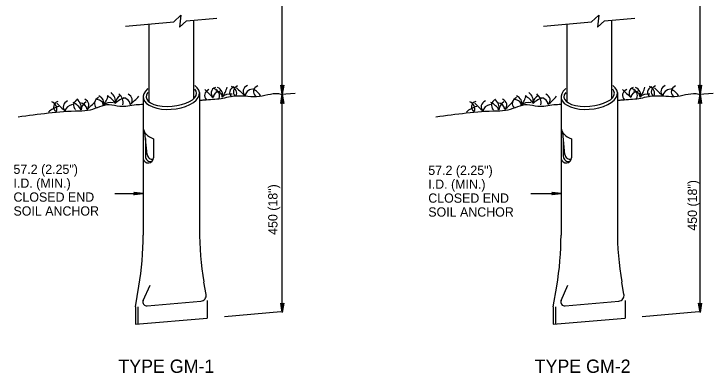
# Model space of a CAD drawing. Extents: x 640253 to 641999, y 298458 to 299646.
# Drawn here: x 640664.1 to 640890, y 299353.4 to 299469.6 of the extents above; entities that cross this region are included whole.
import ezdxf

# ---------------------------------------------------------------- set-up
doc = ezdxf.new("R2010")
doc.units = 0
doc.layers.add('2', color=7, linetype='Continuous')

msp = doc.modelspace()

# ---------------------------------------------------------------- linework, layer by layer
at = {"layer": '2'}
for p, q in [((640750.8, 299443.58), (640750.8, 299512.4)), ((640885.87, 299443.58), (640885.87, 299512.4)), ((640715.71, 299466.98), (640718.01, 299469.2)), ((640718.01, 299469.2), (640717.61, 299465.31)), ((640719.88, 299467.35), (640729.7, 299468.21)), ((640850.79, 299466.98), (640853.09, 299469.2)), ((640853.09, 299469.2), (640852.69, 299465.31)), ((640854.96, 299467.35), (640864.78, 299468.21)), ((640700.17, 299465.61), (640715.71, 299466.98)), ((640707.71, 299466.28), (640707.71, 299441.18)), ((640717.61, 299465.31), (640719.88, 299467.35)), ((640722.17, 299467.55), (640722.17, 299442.19)), ((640835.25, 299465.61), (640850.79, 299466.98)), ((640842.79, 299466.28), (640842.79, 299441.18)), ((640852.69, 299465.31), (640854.96, 299467.35)), ((640857.25, 299467.55), (640857.25, 299442.19)), ((640724.04, 299444.16), (640724.04, 299399.89)), ((640750.5, 299443.61), (640754.97, 299444)), ((640750.8, 299373), (640750.8, 299443.58)), ((640859.12, 299444.16), (640859.12, 299399.89)), ((640885.57, 299443.61), (640890.05, 299444)), ((640885.87, 299373), (640885.87, 299443.58)), ((640705.85, 299442.57), (640705.85, 299398.05)), ((640840.92, 299442.57), (640840.92, 299398.05)), ((640707.11, 299424.14), (640706.38, 299431.28)), ((640706.58, 299429.29), (640706.58, 299423.53)), ((640842.19, 299424.14), (640841.45, 299431.28)), ((640841.66, 299429.29), (640841.66, 299423.53)), ((640709.23, 299429.14), (640709.23, 299423.08)), ((640844.31, 299429.14), (640844.31, 299423.08)), ((640696.66, 299411.48), (640705.85, 299411.48)), ((640831.11, 299411.48), (640840.92, 299411.48)), ((640705.88, 299376.89), (640708.08, 299381.83)), ((640726.2, 299378.84), (640725.5, 299382.86)), ((640840.96, 299376.89), (640843.16, 299381.83)), ((640861.27, 299378.84), (640860.58, 299382.86)), ((640703.35, 299374.8), (640704.47, 299381.53)), ((640838.42, 299374.8), (640839.55, 299381.53)), ((640707.13, 299375.13), (640724.51, 299376.66)), ((640726.54, 299376.84), (640726.54, 299371.21)), ((640842.21, 299375.13), (640859.59, 299376.66)), ((640861.62, 299376.84), (640861.62, 299371.21)), ((640703.35, 299374.8), (640703.35, 299369.18)), ((640704.1, 299374.8), (640704.1, 299369.18)), ((640732.12, 299371.7), (640750.34, 299373.3)), ((640838.42, 299374.8), (640838.42, 299369.18)), ((640839.17, 299374.8), (640839.17, 299369.18)), ((640867.2, 299371.7), (640885.42, 299373.3)), ((640703.35, 299369.18), (640726.54, 299371.21)), ((640838.42, 299369.18), (640861.62, 299371.21))]:
    msp.add_line(p, q, dxfattribs=at)
for points in [[(640751.15, 299446.43), (640750.95, 299446.33), (640750.8, 299443.58), (640751.15, 299446.43), (640751.28, 299446.58), (640750.8, 299443.58), (640750.66, 299446.33), (640750.46, 299446.43), (640750.8, 299443.58), (640750.32, 299446.58), (640750.46, 299446.43)], [(640886.23, 299446.43), (640886.03, 299446.33), (640885.87, 299443.58), (640886.23, 299446.43), (640886.36, 299446.58), (640885.87, 299443.58), (640885.74, 299446.33), (640885.54, 299446.43), (640885.87, 299443.58), (640885.4, 299446.58), (640885.54, 299446.43)], [(640750.44, 299440.73), (640750.64, 299440.83), (640750.8, 299443.58), (640750.44, 299440.73), (640750.31, 299440.58), (640750.8, 299443.58), (640750.93, 299440.83), (640751.14, 299440.73), (640750.8, 299443.58), (640751.27, 299440.58), (640751.14, 299440.73)], [(640885.52, 299440.73), (640885.72, 299440.83), (640885.87, 299443.58), (640885.52, 299440.73), (640885.39, 299440.58), (640885.87, 299443.58), (640886.01, 299440.83), (640886.21, 299440.73), (640885.87, 299443.58), (640886.35, 299440.58), (640886.21, 299440.73)], [(640702.99, 299411.84), (640703.1, 299411.63), (640705.85, 299411.48), (640702.99, 299411.84), (640702.85, 299411.97), (640705.85, 299411.48), (640703.1, 299411.35), (640703, 299411.14), (640705.85, 299411.48), (640702.85, 299411.01), (640703, 299411.14)], [(640838.07, 299411.84), (640838.18, 299411.63), (640840.92, 299411.48), (640838.07, 299411.84), (640837.92, 299411.97), (640840.92, 299411.48), (640838.18, 299411.35), (640838.08, 299411.14), (640840.92, 299411.48), (640837.92, 299411.01), (640838.08, 299411.14)], [(640751.15, 299375.85), (640750.95, 299375.75), (640750.8, 299373), (640751.15, 299375.85), (640751.28, 299376), (640750.8, 299373), (640750.66, 299375.75), (640750.46, 299375.85), (640750.8, 299373), (640750.32, 299376), (640750.46, 299375.85)], [(640886.23, 299375.85), (640886.03, 299375.75), (640885.87, 299373), (640886.23, 299375.85), (640886.36, 299376), (640885.87, 299373), (640885.74, 299375.75), (640885.54, 299375.85), (640885.87, 299373), (640885.4, 299376), (640885.54, 299375.85)]]:
    msp.add_lwpolyline(points, dxfattribs=at)
for centre, radius, start, end in [((640707.52, 299423.08), 1.71, 192.66, 0.0738), ((640708.29, 299423.53), 1.71, 179.9932, 284.9823), ((640708.82, 299424.32), 1.71, 185.8874, 282.1164), ((640842.6, 299423.08), 1.71, 192.66, 0.0738), ((640843.37, 299423.53), 1.71, 179.9932, 284.9823), ((640843.89, 299424.32), 1.71, 185.8874, 282.1164), ((640824.04, 299399.89), 100, 180, 189.8017), ((640959.12, 299399.89), 100, 180, 189.8017), ((640605.85, 299398.04), 100, 350.4939, 0), ((640740.92, 299398.04), 100, 350.4939, 0), ((640724.35, 299378.52), 1.88, 275.0167, 9.777), ((640859.43, 299378.52), 1.88, 275.0167, 9.777), ((640707.02, 299376.38), 1.25, 156.0017, 275.0122), ((640842.1, 299376.38), 1.25, 156.0017, 275.0122)]:
    msp.add_arc(centre, radius, start, end, dxfattribs=at)
for centre, major_axis, ratio, start_param, end_param in [((640714.94, 299443.36), (9.1, 0.8), 0.505377, 2.51251, 6.824211), ((640714.94, 299443.36), (8.14, 0.71), 0.446872, 5.874248, 6.61394), ((640728.37, 299443.25), (-2.67, 0), 0.81, 5.220291, 6.986898), ((640758.27, 299465.19), (-40.88, 0), 0.81, 0.65051, 0.753153), ((640730.48, 299443.94), (-2.67, 0), 0.81, 5.220291, 6.986898), ((640727.37, 299443.11), (3.17, 0), 0.81, 5.950888, 7.353079), ((640728.37, 299443.53), (3.17, 0), 0.81, 5.950888, 7.353079), ((640721.23, 299447.88), (12, 0), 0.81, 5.719284, 6.075734), ((640736.45, 299444.15), (-2.67, 0), 0.81, 5.220291, 6.986898), ((640732.91, 299443.89), (3.17, 0), 0.81, 5.950888, 7.353079), ((640737.67, 299444.4), (-2.67, 0), 0.81, 5.220291, 6.986898), ((640768.6, 299465.78), (-40.88, 0), 0.81, 0.65051, 0.753153), ((640740.82, 299444.53), (-2.67, 0), 0.81, 5.220291, 6.986898), ((640741.53, 299443.02), (-2.76, 0), 0.81, 4.863472, 6.233126), ((640737.48, 299440.47), (7.12, 0), 0.81, 0.438834, 0.99788), ((640744.16, 299444.4), (-2.67, 0), 0.81, 5.220291, 6.986898), ((640850.02, 299443.36), (9.1, 0.8), 0.505377, 2.51251, 6.824211), ((640850.02, 299443.36), (8.14, 0.71), 0.446872, 5.874248, 6.61394), ((640863.44, 299443.25), (-2.67, 0), 0.81, 5.220291, 6.986898), ((640893.35, 299465.19), (-40.88, 0), 0.81, 0.65051, 0.753153), ((640865.56, 299443.94), (-2.67, 0), 0.81, 5.220291, 6.986898), ((640862.45, 299443.11), (3.17, 0), 0.81, 5.950888, 7.353079), ((640863.45, 299443.53), (3.17, 0), 0.81, 5.950888, 7.353079), ((640856.31, 299447.88), (12, 0), 0.81, 5.719284, 6.075734), ((640871.52, 299444.15), (-2.67, 0), 0.81, 5.220291, 6.986898), ((640867.99, 299443.89), (3.17, 0), 0.81, 5.950888, 7.353079), ((640872.75, 299444.4), (-2.67, 0), 0.81, 5.220291, 6.986898), ((640903.68, 299465.78), (-40.88, 0), 0.81, 0.65051, 0.753153), ((640875.9, 299444.53), (-2.67, 0), 0.81, 5.220291, 6.986898), ((640876.61, 299443.02), (-2.76, 0), 0.81, 4.863472, 6.233126), ((640872.56, 299440.47), (7.12, 0), 0.81, 0.438834, 0.99788), ((640879.23, 299444.4), (-2.67, 0), 0.81, 5.220291, 6.986898), ((640689.95, 299440.82), (3.17, 0), 0.81, 5.950888, 7.353079), ((640682.81, 299445.17), (12, 0), 0.81, 5.719284, 6.075734), ((640690.38, 299438.2), (7.12, 0), 0.81, 0.438834, 0.99788), ((640691.96, 299441.33), (4.93, 0), 0.81, 6.111626, 7.062961), ((640701.43, 299440.4), (-4.62, 0), 0.81, 5.422128, 6.217327), ((640694.47, 299440.9), (4.93, 0), 0.81, 6.111626, 7.062961), ((640699.66, 299441.74), (2.67, 0), 0.81, 5.579472, 7.346079), ((640671.87, 299462.99), (40.88, 0), 0.81, 5.530032, 5.632675), ((640714.94, 299443.36), (8.14, 0.71), 0.446872, 2.733251, 5.87413), ((640731.2, 299442.43), (-2.76, 0), 0.81, 4.863472, 6.233126), ((640729.17, 299442.8), (2.21, 0), 0.81, 6.222188, 7.802691), ((640733.75, 299441.32), (-2.92, 0), 0.81, 4.426104, 5.665423), ((640825.03, 299440.82), (3.17, 0), 0.81, 5.950888, 7.353079), ((640817.89, 299445.17), (12, 0), 0.81, 5.719284, 6.075734), ((640825.45, 299438.2), (7.12, 0), 0.81, 0.438834, 0.99788), ((640827.04, 299441.33), (4.93, 0), 0.81, 6.111626, 7.062961), ((640836.51, 299440.4), (-4.62, 0), 0.81, 5.422128, 6.217327), ((640829.55, 299440.9), (4.93, 0), 0.81, 6.111626, 7.062961), ((640834.74, 299441.74), (2.67, 0), 0.81, 5.579472, 7.346079), ((640806.95, 299462.99), (40.88, 0), 0.81, 5.530032, 5.632675), ((640850.02, 299443.36), (8.14, 0.71), 0.446872, 2.733251, 5.87413), ((640866.28, 299442.43), (-2.76, 0), 0.81, 4.863472, 6.233126), ((640864.25, 299442.8), (2.21, 0), 0.81, 6.222188, 7.802691), ((640868.83, 299441.32), (-2.92, 0), 0.81, 4.426104, 5.665423), ((640674.79, 299438.91), (3.17, 0), 0.81, 5.950888, 7.353079), ((640679.55, 299439.42), (-2.67, 0), 0.81, 5.220291, 6.986898), ((640710.48, 299460.8), (-40.88, 0), 0.81, 0.65051, 0.753153), ((640682.7, 299439.55), (-2.67, 0), 0.81, 5.220291, 6.986898), ((640679.33, 299436.11), (7.12, 0), 0.81, 0.438834, 0.99788), ((640686, 299440.04), (-2.67, 0), 0.81, 5.220291, 6.986898), ((640680.91, 299439.24), (4.93, 0), 0.81, 6.111626, 7.062961), ((640684.94, 299438.61), (2.76, 0), 0.81, 0.050059, 1.419713), ((640690.38, 299438.31), (-4.62, 0), 0.81, 5.422128, 6.217327), ((640685.65, 299440.12), (2.67, 0), 0.81, 5.579472, 7.346079), ((640657.87, 299461.37), (40.88, 0), 0.81, 5.530032, 5.632675), ((640692.75, 299440.62), (-2.67, 0), 0.81, 5.220291, 6.986898), ((640690.75, 299440.09), (2.21, 0), 0.81, 6.222188, 7.802691), ((640695.33, 299438.61), (-2.92, 0), 0.81, 4.426104, 5.665423), ((640702.01, 299437.27), (-6.66, 0), 0.81, 4.996122, 5.605504), ((640698.94, 299440.23), (2.76, 0), 0.81, 0.050059, 1.419713), ((640809.87, 299438.91), (3.17, 0), 0.81, 5.950888, 7.353079), ((640814.63, 299439.42), (-2.67, 0), 0.81, 5.220291, 6.986898), ((640845.56, 299460.8), (-40.88, 0), 0.81, 0.65051, 0.753153), ((640817.77, 299439.55), (-2.67, 0), 0.81, 5.220291, 6.986898), ((640814.41, 299436.11), (7.12, 0), 0.81, 0.438834, 0.99788), ((640821.08, 299440.04), (-2.67, 0), 0.81, 5.220291, 6.986898), ((640815.99, 299439.24), (4.93, 0), 0.81, 6.111626, 7.062961), ((640820.02, 299438.61), (2.76, 0), 0.81, 0.050059, 1.419713), ((640825.46, 299438.31), (-4.62, 0), 0.81, 5.422128, 6.217327), ((640820.73, 299440.12), (2.67, 0), 0.81, 5.579472, 7.346079), ((640792.95, 299461.37), (40.88, 0), 0.81, 5.530032, 5.632675), ((640827.83, 299440.62), (-2.67, 0), 0.81, 5.220291, 6.986898), ((640825.83, 299440.09), (2.21, 0), 0.81, 6.222188, 7.802691), ((640830.41, 299438.61), (-2.92, 0), 0.81, 4.426104, 5.665423), ((640837.08, 299437.27), (-6.66, 0), 0.81, 4.996122, 5.605504), ((640834.02, 299440.23), (2.76, 0), 0.81, 0.050059, 1.419713), ((640680.44, 299434.45), (-6.66, 0), 0.81, 4.996122, 5.605504), ((640683.41, 299438.04), (-2.76, 0), 0.81, 4.863472, 6.233126), ((640815.52, 299434.45), (-6.66, 0), 0.81, 4.996122, 5.605504), ((640818.49, 299438.04), (-2.76, 0), 0.81, 4.863472, 6.233126), ((640716.76, 299433.65), (10.92, 0.96), 0.505377, 3.143506, 3.907964), ((640851.84, 299433.65), (10.92, 0.96), 0.505377, 3.143506, 3.907964)]:
    msp.add_ellipse(centre, major_axis=major_axis, ratio=ratio, start_param=start_param, end_param=end_param, dxfattribs=at)
for points in [[(640724.38, 299441.66), (640725.56, 299441.78), (640731.03, 299442.26), (640735.93, 299443.11), (640743.46, 299442.97), (640750.39, 299443.64), (640750.51, 299443.6)], [(640859.46, 299441.66), (640860.64, 299441.78), (640866.11, 299442.26), (640871.01, 299443.11), (640878.54, 299442.97), (640885.46, 299443.64), (640885.59, 299443.6)], [(640665.43, 299436.35), (640685.08, 299438.26), (640688.79, 299438.6), (640694.87, 299440.29), (640698.3, 299439.75), (640703.54, 299440.26), (640705.85, 299440.36)], [(640800.5, 299436.35), (640820.15, 299438.26), (640823.87, 299438.6), (640829.95, 299440.29), (640833.38, 299439.75), (640838.62, 299440.26), (640840.92, 299440.36)]]:
    msp.add_spline(points, degree=3, dxfattribs=at)

# ---------------------------------------------------------------- texts
for s, height, p in [('57.2 (2.25")', 3, (640663.93, 299417.84)), ('57.2 (2.25")', 3, (640798.01, 299417.51)), ('I.D. (MIN.)', 3, (640663.93, 299413.34)), ('I.D. (MIN.)', 3, (640798.01, 299413.01)), ('CLOSED END', 3, (640663.93, 299408.84)), ('CLOSED END', 3, (640798.01, 299408.51)), ('SOIL ANCHOR', 3, (640663.93, 299404.34)), ('SOIL ANCHOR', 3, (640798.01, 299404.01)), ('TYPE GM-1', 4.3, (640697.84, 299353.47)), ('TYPE GM-2', 4.3, (640832.41, 299353.47))]:
    msp.add_text(s, height=height, dxfattribs=at).set_placement(p)
for p in [(640749.26, 299398.11), (640884.86, 299399.47)]:
    msp.add_text('450 (18")', height=3, rotation=90, dxfattribs=at).set_placement(p)

doc.saveas('drawing.dxf')
